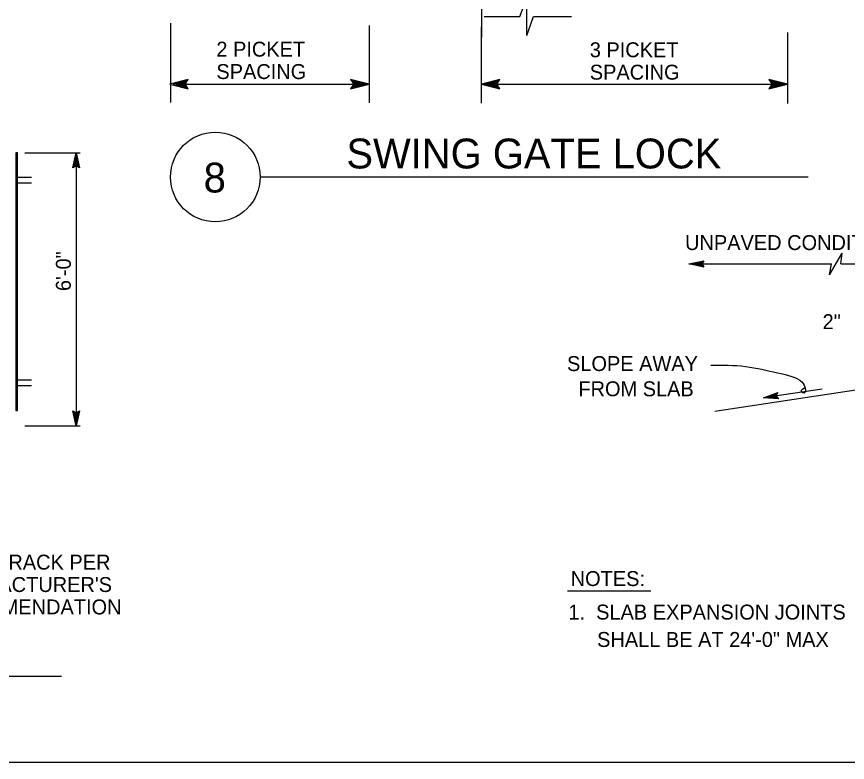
# Model space of a CAD drawing. Extents: x 6710407 to 6714861, y 1868090 to 1871317.
# Drawn here: x 6712474.7 to 6712808.6, y 1869155.1 to 1869454.7 of the extents above; entities that cross this region are included whole.
import ezdxf

# ---------------------------------------------------------------- set-up
doc = ezdxf.new("R2010")
doc.units = 0
for name, color, linetype in [('G-MARK', 7, 'Continuous'), ('G-TEXT', 7, 'Continuous'), ('G-TTLB-VIEW', 7, 'Continuous'), ('Nongeo Data(60)', 7, 'Continuous'), ('Sndwall Anno(59)', 7, 'Continuous')]:
    doc.layers.add(name, color=color, linetype=linetype)

# ---------------------------------------------------------------- blocks, each defined once
blk = doc.blocks.new('SHORTN')
at = {"layer": 'Sndwall Anno(59)'}
for p, q in [((-0.00193, 0), (-0.00259, 0.00447)), ((0.00264, -0.00447), (-0.00259, 0.00447)), ((-0.00193, 0), (-0.00193, 0)), ((0.00264, -0.00447), (0.00183, 0)), ((0.00183, 0), (0.00183, 0))]:
    blk.add_line(p, q, dxfattribs=at)

msp = doc.modelspace()

# ---------------------------------------------------------------- linework, layer by layer
at = {"layer": 'G-MARK'}
for p, q in [((6712676.93, 1869454.7), (6712679.67, 1869462.23)), ((6712679.67, 1869447.18), (6712679.67, 1869462.23)), ((6712536.53, 1869452.04), (6712536.53, 1869420.24)), ((6712662.61, 1869454.7), (6712676.93, 1869454.7)), ((6712679.67, 1869447.18), (6712682.41, 1869454.7)), ((6712682.41, 1869454.7), (6712697.65, 1869454.7)), ((6712616.45, 1869420.07), (6712616.45, 1869451.2)), ((6712661.53, 1869419.98), (6712661.53, 1869450.63)), ((6712784.45, 1869448.37), (6712784.45, 1869419.73)), ((6712541.12, 1869427.57), (6712616.3, 1869427.57)), ((6712661.53, 1869427.57), (6712784.45, 1869427.57)), ((6712477.94, 1869400.01), (6712500.29, 1869400.01)), ((6712498.57, 1869400.01), (6712498.57, 1869290.28)), ((6712744.85, 1869355.31), (6712802.18, 1869355.31)), ((6712805.88, 1869355.31), (6712840.41, 1869355.31)), ((6712798.44, 1869305.05), (6712774.85, 1869301.51)), ((6712477.94, 1869290.28), (6712500.29, 1869290.28))]:
    msp.add_line(p, q, dxfattribs=at)
msp.add_open_spline([(6712753.65, 1869314.63), (6712756.11, 1869314.68), (6712766.35, 1869314.88), (6712778.91, 1869311.87), (6712791.43, 1869309.34), (6712792.21, 1869302.29), (6712789.13, 1869304.34), (6712790.77, 1869305.3), (6712791.72, 1869305.86)], degree=3, dxfattribs=at)
at = {"layer": 'G-TEXT'}
for p, q in [((6712497.23, 1869394.01), (6712498.57, 1869400.01)), ((6712497.59, 1869394.23), (6712498.57, 1869398.63)), ((6712498.57, 1869400.01), (6712498.57, 1869400.01)), ((6712498.57, 1869400.01), (6712499.9, 1869394.01)), ((6712498.58, 1869398.62), (6712499.54, 1869394.25)), ((6712497.95, 1869394.46), (6712498.57, 1869397.25)), ((6712498.3, 1869394.64), (6712498.57, 1869395.87)), ((6712498.57, 1869397.25), (6712499.2, 1869394.42)), ((6712498.57, 1869395.87), (6712498.84, 1869394.66)), ((6712498.57, 1869394.81), (6712497.23, 1869394.01)), ((6712497.23, 1869394.01), (6712497.23, 1869394.01)), ((6712499.9, 1869394.01), (6712498.57, 1869394.81)), ((6712499.9, 1869394.01), (6712499.9, 1869394.01)), ((6712744.85, 1869355.31), (6712750.85, 1869356.64)), ((6712750.85, 1869353.97), (6712744.85, 1869355.31)), ((6712744.85, 1869355.31), (6712744.85, 1869355.31)), ((6712750.64, 1869354.33), (6712746.23, 1869355.31)), ((6712746.24, 1869355.32), (6712750.62, 1869356.28)), ((6712747.62, 1869355.31), (6712750.44, 1869355.94)), ((6712750.4, 1869354.69), (6712747.62, 1869355.31)), ((6712749, 1869355.31), (6712750.21, 1869355.58)), ((6712750.23, 1869355.03), (6712749, 1869355.31)), ((6712750.85, 1869356.64), (6712750.05, 1869355.31)), ((6712750.05, 1869355.31), (6712750.85, 1869353.97)), ((6712750.85, 1869356.64), (6712750.85, 1869356.64)), ((6712750.85, 1869353.97), (6712750.85, 1869353.97)), ((6712774.85, 1869301.51), (6712780.58, 1869303.72)), ((6712780.98, 1869301.07), (6712774.85, 1869301.51)), ((6712774.85, 1869301.51), (6712774.85, 1869301.51)), ((6712780.71, 1869301.39), (6712776.21, 1869301.71)), ((6712776.22, 1869301.72), (6712780.4, 1869303.33)), ((6712777.58, 1869301.92), (6712780.28, 1869302.96)), ((6712780.43, 1869301.72), (6712777.58, 1869301.92)), ((6712778.95, 1869302.12), (6712780.1, 1869302.57)), ((6712780.2, 1869302.03), (6712778.95, 1869302.12)), ((6712780.58, 1869303.72), (6712779.99, 1869302.28)), ((6712779.99, 1869302.28), (6712780.98, 1869301.07)), ((6712780.58, 1869303.72), (6712780.58, 1869303.72)), ((6712780.98, 1869301.07), (6712780.98, 1869301.07)), ((6712498.57, 1869290.28), (6712497.24, 1869296.28)), ((6712497.24, 1869296.28), (6712497.24, 1869296.28)), ((6712497.24, 1869296.28), (6712498.57, 1869295.48)), ((6712498.57, 1869291.68), (6712497.6, 1869296.05)), ((6712498.58, 1869293.05), (6712497.95, 1869295.87)), ((6712498.58, 1869294.43), (6712498.31, 1869295.64)), ((6712498.57, 1869295.48), (6712499.91, 1869296.28)), ((6712499.91, 1869296.28), (6712498.57, 1869290.28)), ((6712499.56, 1869296.07), (6712498.57, 1869291.66)), ((6712499.2, 1869295.83), (6712498.58, 1869293.05)), ((6712498.85, 1869295.66), (6712498.58, 1869294.43)), ((6712499.91, 1869296.28), (6712499.91, 1869296.28)), ((6712498.57, 1869290.28), (6712498.57, 1869290.28))]:
    msp.add_line(p, q, dxfattribs=at)
for points in [[(6712536.26, 1869427.57), (6712543.66, 1869425.72), (6712542.43, 1869427.57), (6712543.66, 1869429.42), (6712536.26, 1869427.57)], [(6712537.57, 1869427.57), (6712542.94, 1869426.22), (6712542.05, 1869427.57), (6712542.94, 1869428.92), (6712537.57, 1869427.57)], [(6712538.67, 1869427.57), (6712542.33, 1869426.65), (6712541.72, 1869427.57), (6712542.33, 1869428.49), (6712538.67, 1869427.57)], [(6712616.33, 1869427.57), (6712608.92, 1869429.42), (6712610.15, 1869427.57), (6712608.92, 1869425.72), (6712616.33, 1869427.57)], [(6712615.01, 1869427.57), (6712609.64, 1869428.92), (6712610.54, 1869427.57), (6712609.64, 1869426.22), (6712615.01, 1869427.57)], [(6712613.91, 1869427.57), (6712610.25, 1869428.49), (6712610.86, 1869427.57), (6712610.25, 1869426.65), (6712613.91, 1869427.57)], [(6712661.53, 1869427.57), (6712668.94, 1869425.72), (6712667.71, 1869427.57), (6712668.94, 1869429.42), (6712661.53, 1869427.57)], [(6712661.53, 1869427.57), (6712668.94, 1869425.72), (6712667.71, 1869427.57), (6712668.94, 1869429.42), (6712661.53, 1869427.57)], [(6712662.85, 1869427.57), (6712668.22, 1869426.22), (6712667.32, 1869427.57), (6712668.22, 1869428.92), (6712662.85, 1869427.57)], [(6712662.85, 1869427.57), (6712668.22, 1869426.22), (6712667.32, 1869427.57), (6712668.22, 1869428.92), (6712662.85, 1869427.57)], [(6712663.95, 1869427.57), (6712667.61, 1869426.65), (6712667, 1869427.57), (6712667.61, 1869428.49), (6712663.95, 1869427.57)], [(6712663.95, 1869427.57), (6712667.61, 1869426.65), (6712667, 1869427.57), (6712667.61, 1869428.49), (6712663.95, 1869427.57)], [(6712784.45, 1869427.57), (6712777.04, 1869429.42), (6712778.27, 1869427.57), (6712777.04, 1869425.72), (6712784.45, 1869427.57)], [(6712783.13, 1869427.57), (6712777.76, 1869428.92), (6712778.66, 1869427.57), (6712777.76, 1869426.22), (6712783.13, 1869427.57)], [(6712782.03, 1869427.57), (6712778.37, 1869428.49), (6712778.98, 1869427.57), (6712778.37, 1869426.65), (6712782.03, 1869427.57)], [(6712539.58, 1869427.57), (6712541.83, 1869427), (6712541.46, 1869427.57), (6712541.83, 1869428.14), (6712539.58, 1869427.57)], [(6712539.64, 1869427.8), (6712541.3, 1869427.38), (6712541.18, 1869427.57), (6712541.3, 1869427.76), (6712539.64, 1869427.34)], [(6712613, 1869427.57), (6712610.75, 1869428.14), (6712611.12, 1869427.57), (6712610.75, 1869427), (6712613, 1869427.57)], [(6712612.94, 1869427.34), (6712611.28, 1869427.76), (6712611.4, 1869427.57), (6712611.28, 1869427.38), (6712612.94, 1869427.8)], [(6712664.86, 1869427.57), (6712667.11, 1869427), (6712666.74, 1869427.57), (6712667.11, 1869428.14), (6712664.86, 1869427.57)], [(6712664.86, 1869427.57), (6712667.11, 1869427), (6712666.74, 1869427.57), (6712667.11, 1869428.14), (6712664.86, 1869427.57)], [(6712664.92, 1869427.8), (6712666.58, 1869427.38), (6712666.45, 1869427.57), (6712666.58, 1869427.76), (6712664.92, 1869427.34)], [(6712664.92, 1869427.8), (6712666.58, 1869427.38), (6712666.45, 1869427.57), (6712666.58, 1869427.76), (6712664.92, 1869427.34)], [(6712781.12, 1869427.57), (6712778.87, 1869428.14), (6712779.24, 1869427.57), (6712778.87, 1869427), (6712781.12, 1869427.57)], [(6712781.06, 1869427.34), (6712779.4, 1869427.76), (6712779.52, 1869427.57), (6712779.4, 1869427.38), (6712781.06, 1869427.8)]]:
    msp.add_lwpolyline(points, dxfattribs=at)
at = {"layer": 'G-TTLB-VIEW'}
msp.add_lwpolyline([(6711433.78, 1870605.06), (6713227.53, 1870605.06), (6713227.53, 1869155.06), (6711433.78, 1869155.06)], close=True, dxfattribs=at)
at = {"layer": 'Nongeo Data(60)'}
for p, q in [((6712661.48, 1869549.03), (6712661.48, 1869446.38)), ((6712480.69, 1869390.11), (6712475.07, 1869390.11)), ((6712792.85, 1869390.26), (6712572.54, 1869390.26)), ((6712480.69, 1869387.82), (6712475.07, 1869387.82)), ((6712480.69, 1869308.57), (6712475.07, 1869308.57)), ((6712840.37, 1869308.86), (6712755.29, 1869296.08)), ((6712480.69, 1869306.29), (6712475.07, 1869306.29)), ((6712696.09, 1869223.98), (6712729.57, 1869223.98)), ((6712492.77, 1869189.52), (6712165.79, 1869189.52))]:
    msp.add_line(p, q, dxfattribs=at)
msp.add_lwpolyline([(6712474.31, 1869296.38), (6712475.07, 1869296.38), (6712475.07, 1869400.01), (6712474.31, 1869400.01)], close=True, dxfattribs=at)
msp.add_circle((6712554.54, 1869390.26), 18, dxfattribs=at)

# ---------------------------------------------------------------- block references
at = {"layer": 'G-MARK', "xscale": 984.251968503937, "yscale": -984.251968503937, "rotation": 180}
msp.add_blockref('SHORTN', (6712803.98, 1869355.32), dxfattribs=at)

# ---------------------------------------------------------------- texts
at = {"layer": 'Nongeo Data(60)'}
for s, height, p in [('2 PICKET', 6, (6712554.97, 1869438.62)), ('3 PICKET', 6, (6712705.03, 1869438.38)), ('SPACING', 6, (6712554.97, 1869429.62)), ('SPACING', 6, (6712705.03, 1869429.38)), ('SWING GATE LOCK', 12, (6712607.23, 1869393.7)), ('8', 12, (6712549.85, 1869384.04)), ('UNPAVED CONDITIONS', 6, (6712743.33, 1869360.91)), ('2"', 6, (6712798.6, 1869329.14)), ('SLOPE AWAY', 6, (6712695.89, 1869312.29)), ('FROM SLAB', 6, (6712700.45, 1869302.16)), ('STEEL TRACK PER ', 6, (6712438.83, 1869232.52)), ('NOTES:', 6, (6712697.36, 1869225.91)), ("MANUFACTURER'S", 6, (6712438.83, 1869223.52)), ('RECOMMENDATION', 6, (6712438.83, 1869214.52)), ('1.  SLAB EXPANSION JOINTS', 6, (6712696.43, 1869212.46)), ('SHALL BE AT 24\'-0" MAX', 6, (6712707.98, 1869201.44))]:
    msp.add_text(s, height=height, dxfattribs=at).set_placement(p)
msp.add_text('6\'-0"', height=6, rotation=90, dxfattribs=at).set_placement((6712496.48, 1869344.43))

doc.saveas('drawing.dxf')
